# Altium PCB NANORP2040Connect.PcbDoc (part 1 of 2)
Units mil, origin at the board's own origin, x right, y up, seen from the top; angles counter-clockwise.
Board outline 1700 x 700 mil, 4 copper layers (TOP, GND, SIG, BOTTOM), stack 62.441 mil thick; 92 components, 78 nets, 400 pads, 196 vias.
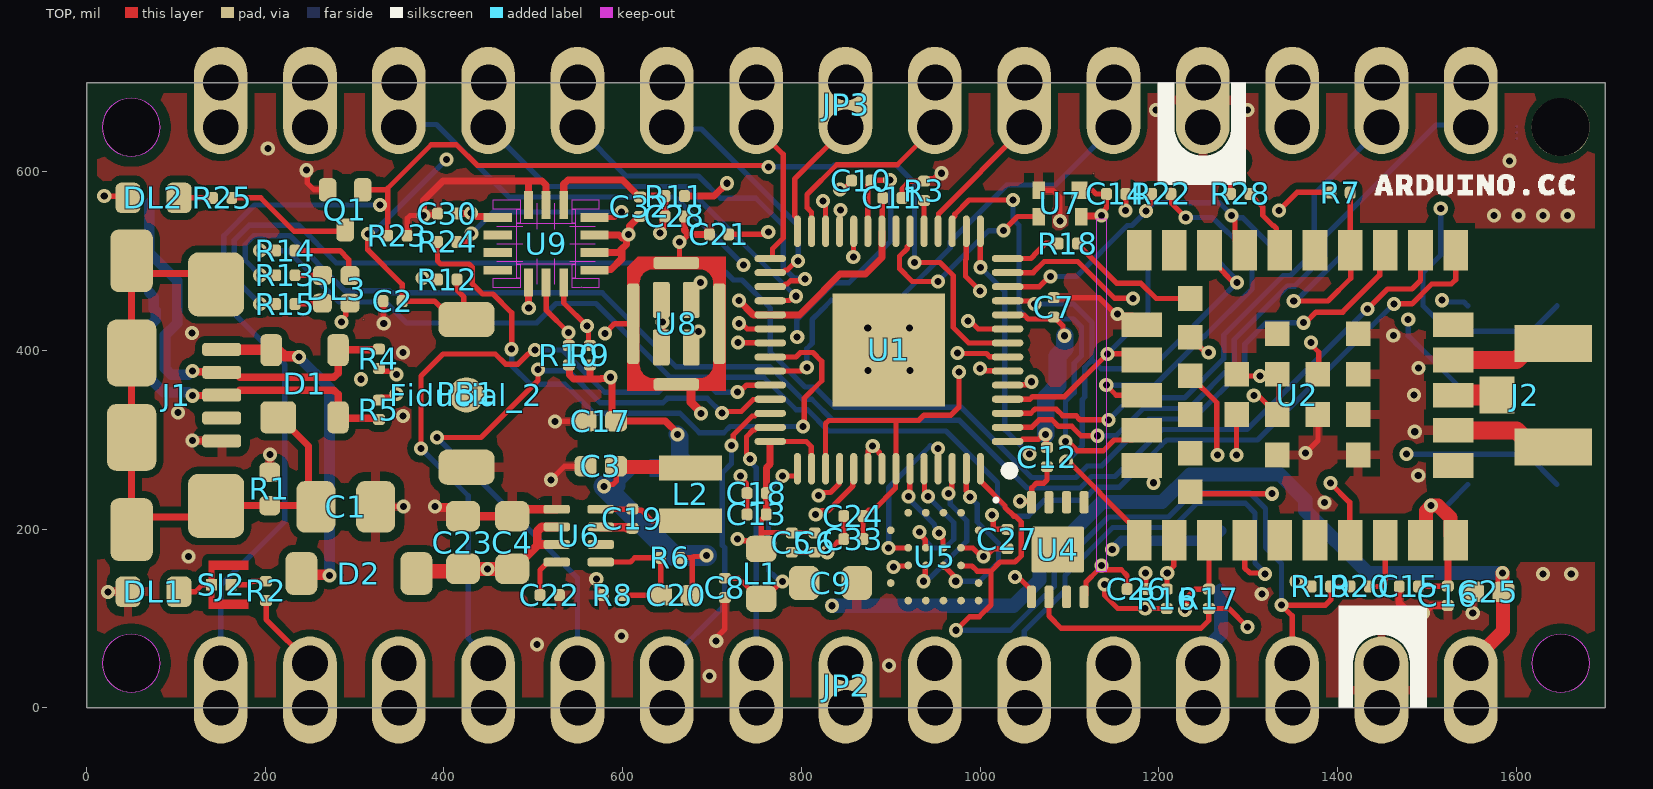
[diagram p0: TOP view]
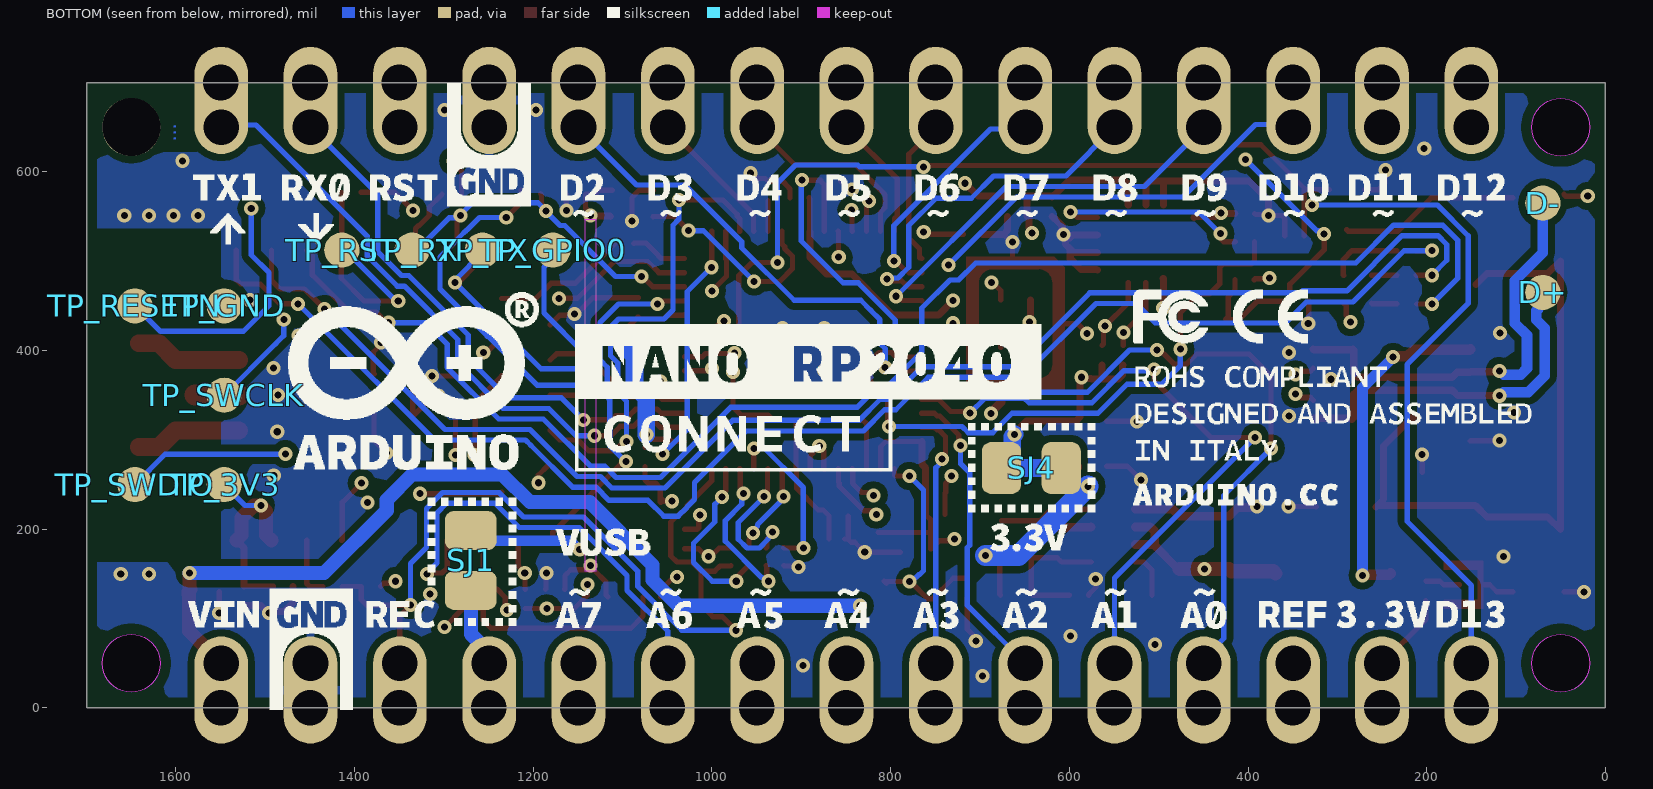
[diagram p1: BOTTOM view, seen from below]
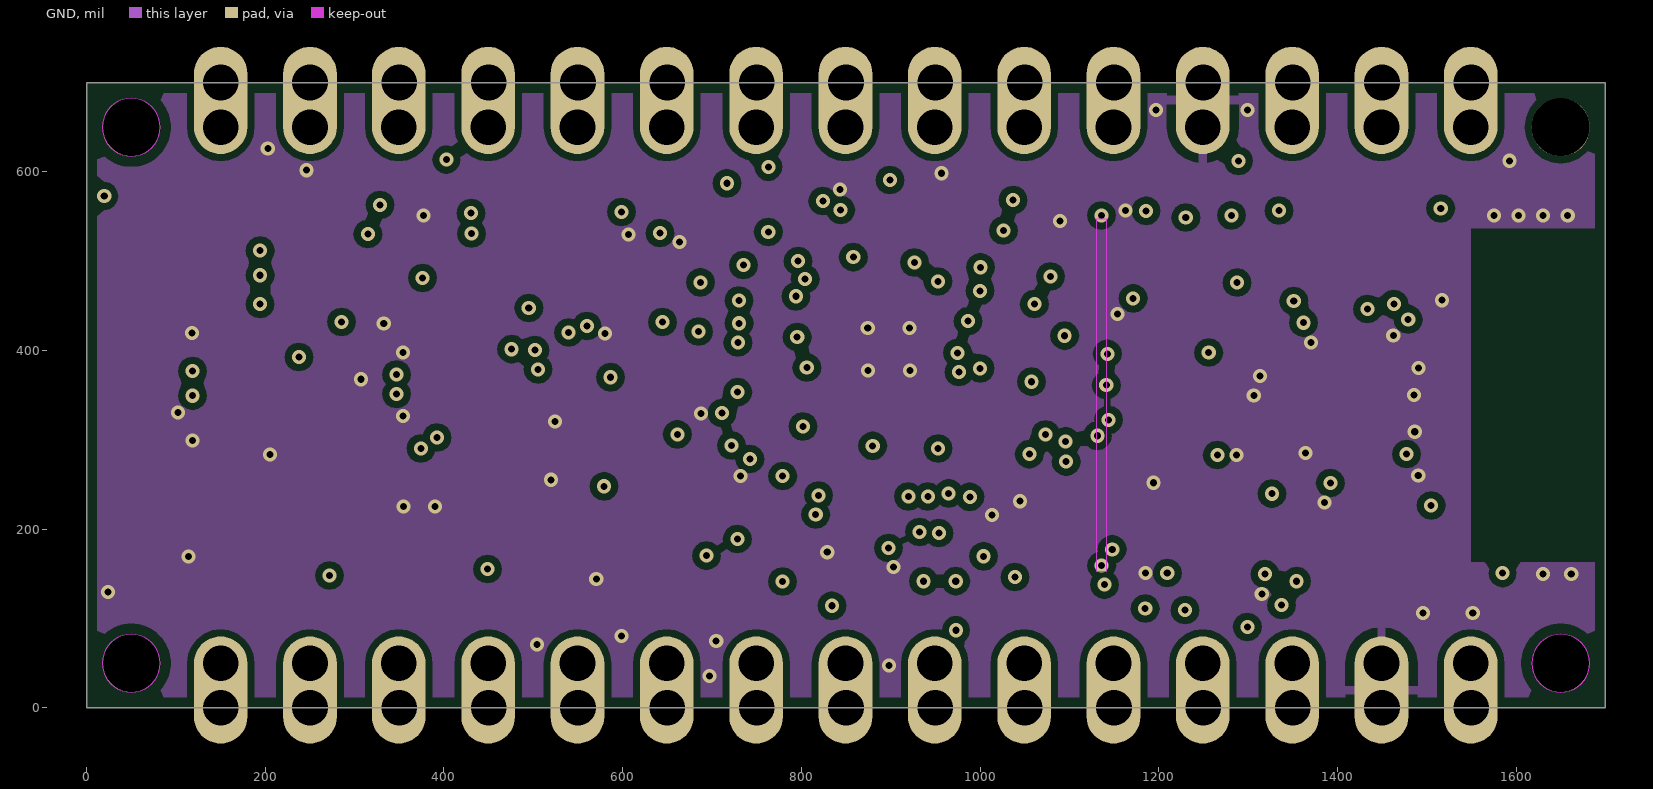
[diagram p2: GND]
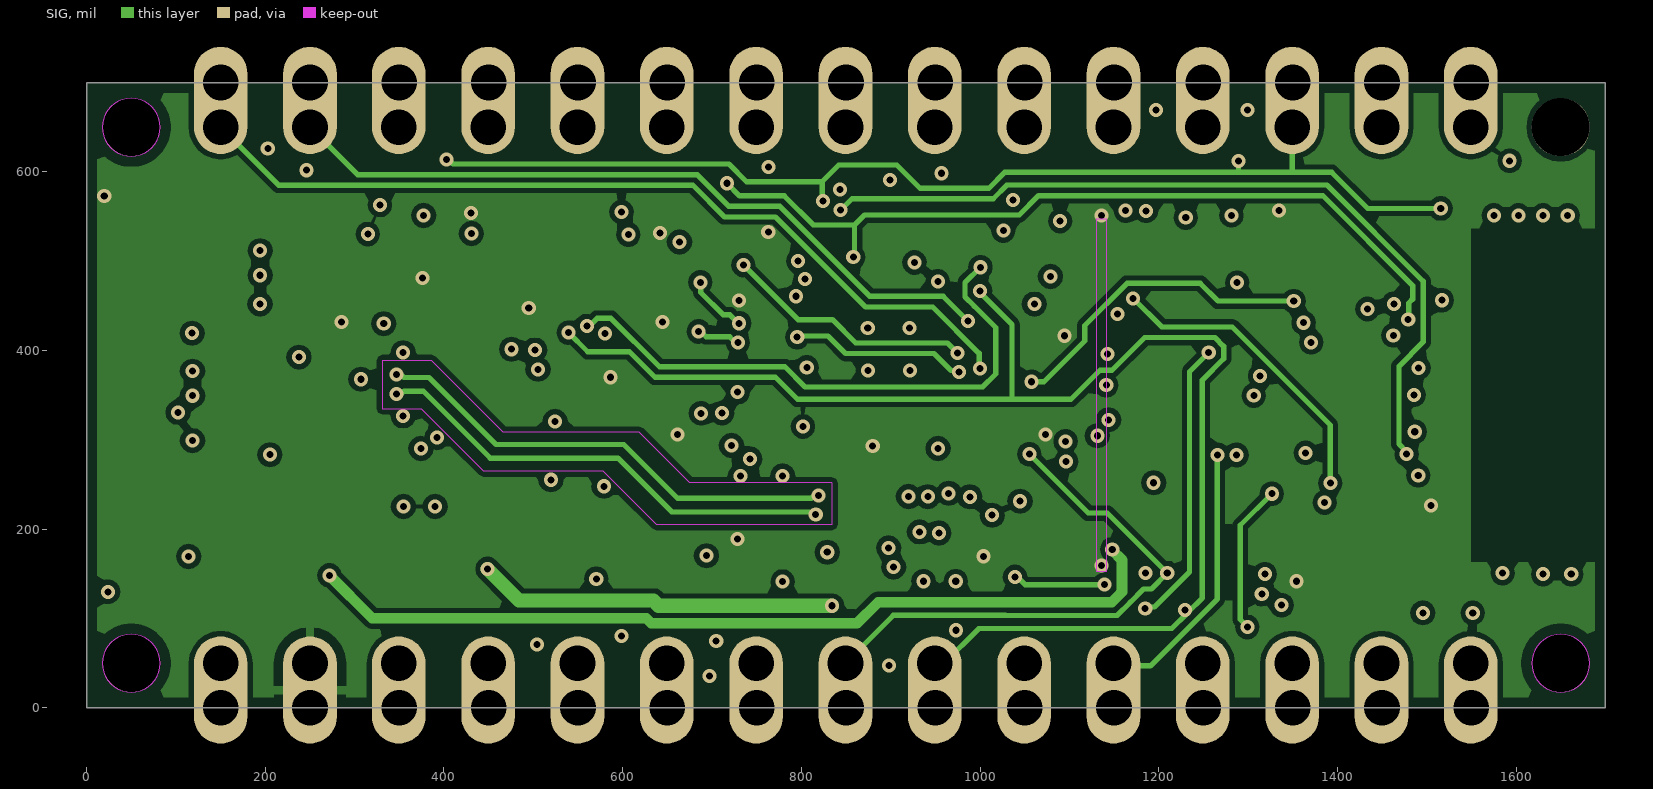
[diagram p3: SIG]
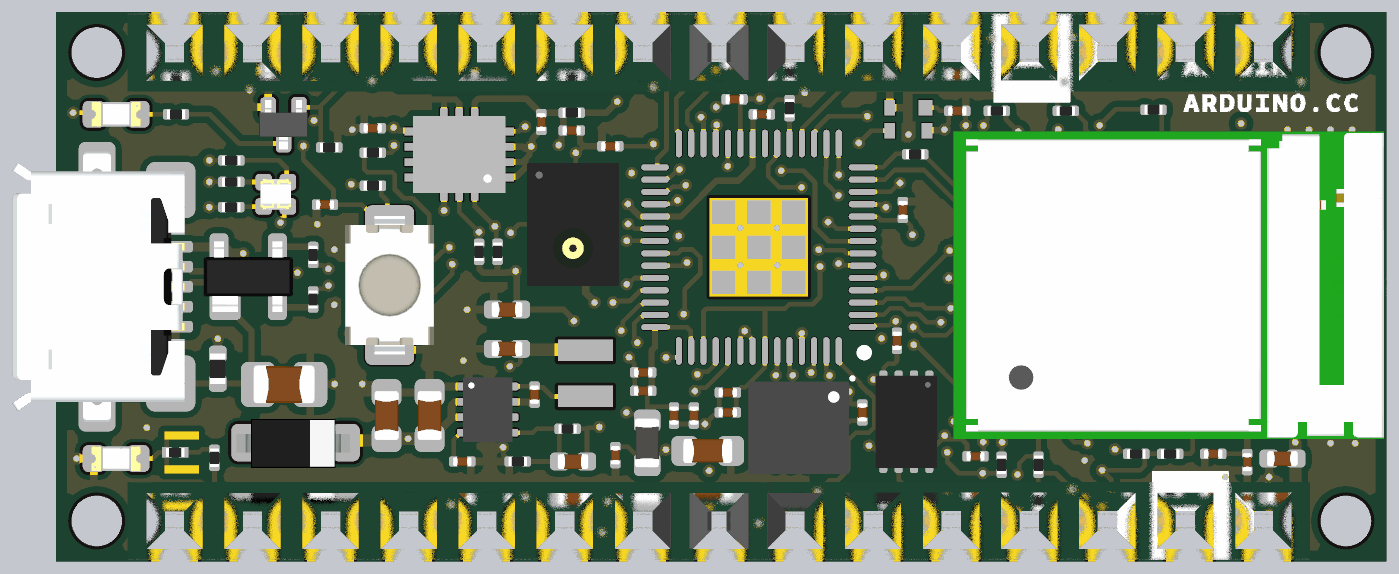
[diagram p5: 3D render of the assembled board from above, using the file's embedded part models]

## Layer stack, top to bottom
Top Solder: solder mask 0.4, Solder Resist, Dk 3.5
TOP: signal copper 0.7087
Dielectric 1: prepreg 5.5118, PP-014, Dk 4.2
GND: signal copper 1.378
Dielectric2: core 47.2441, FR-4, Dk 4.8
SIG: signal copper 1.378
Dielectric3: prepreg 5.5118, PP-014, Dk 4.2
BOTTOM: signal copper 0.7087
Bottom Solder: solder mask 0.4, Solder Resist, Dk 3.5

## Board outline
1700,0 0,0 0,700 1700,700
cut-out: 1650,17.5 ccw(c1650,50) 1682.5,50 ccw(c1650,50) 1650,82.5 ccw(c1650,50) 1617.5,50 ccw(c1650,50)
cut-out: 50,617.5 ccw(c50,650) 82.5,650 ccw(c50,650) 50,682.5 ccw(c50,650) 17.5,650 ccw(c50,650)
cut-out: 50,17.5 ccw(c50,50) 82.5,50 ccw(c50,50) 50,82.5 ccw(c50,50) 17.5,50 ccw(c50,50)

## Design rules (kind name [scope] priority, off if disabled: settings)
BoardOutlineClearance Silks [(OnLayer('Top Overlay') OR OnLayer('Bottom Overlay'))] p1: gap=0.39 ignorepadtopadclearanceinfootprint=FALSE
BoardOutlineClearance MountingHoles [(ObjectKind = 'Pad') And (Name = 'Free-MH')] p2: gap=0 ignorepadtopadclearanceinfootprint=FALSE
BoardOutlineClearance Header_Castellated [((ObjectKind = 'Pad') And (Component = 'JP2')) OR                                                                                    ((ObjectKind = 'Pad') And (Component = 'JP3'))] p3: gap=0 ignorepadtopadclearanceinfootprint=FALSE
BoardOutlineClearance [All] p4: gap=11.81 ignorepadtopadclearanceinfootprint=FALSE
Clearance GND_POLYGONS [(InNamedPolygon('GND_TOP') OR InNamedPolygon('GND_2') OR InNamedPolygon('GND_3') OR InNamedPolygon('GND_BOT'))] p1: gap=7.87 ignorepadtopadclearanceinfootprint=FALSE
Clearance "Generic clearance 0.15mm" [All] p2: gap=5.91 ignorepadtopadclearanceinfootprint=FALSE
ComponentClearance NINA-UFL [InComponent('U2') vs InComponent('J2')] p1: gap=0 collisioncheckmode=3 verticalgap=0 showdistances=FALSE
ComponentClearance [All] p2: gap=0 collisioncheckmode=3 verticalgap=0 showdistances=FALSE
DiffPairsRouting [InDifferentialPairClass('USB')] p1: maxlimit=10 minlimit=5.91 mostfreqgap=10 toplayer_maxgap=5.91 toplayer_prefgap=5.91 toplayer_minwidth=5.91 toplayer_maxwidth=8.27 toplayer_prefwidth=8.27 midlayer14_mingap=9.45 midlayer14_maxgap=9.45 midlayer14_prefgap=9.45 midlayer14_minwidth=5.91 midlayer14_maxwidth=5.91 midlayer14_prefwidth=5.91 bottomlayer_maxgap=5.91 bottomlayer_prefgap=5.91 bottomlayer_minwidth=8.27 bottomlayer_maxwidth=8.27 bottomlayer_prefwidth=8.27 impedanceprofiledriven=TRUE impedanceprofileid={C5D8398E-BCA5-4495-8332-5063613C51E1} impedanceprofilevalue=90.000000 maxuncoupledlength=500
HoleSize [All] p1: absolutevalues=TRUE maxlimit=236.22 minlimit=7.87 maxpercent=80.000 minpercent=20.000
HoleToHoleClearance [All] p1: gap=9.84 allowstackedmicrovias=TRUE
MinimumAnnularRing [All] p1: minimumring=3.94
MinimumSolderMaskSliver [All] p1: minsoldermaskwidth=3.94
NetAntennae Inductor [(ObjectKind = 'Component') And (Comment = 'MAKK2016T3R3M')] p1: netantennaetolerance=393.7
NetAntennae [All] p2: netantennaetolerance=0
PolygonConnect [All] p1: thpad.connectstyle=Relief thpad.reliefconductorwidth=10 thpad.reliefentries=4 thpad.polygonreliefangle="90 Angle" thpad.airgapwidth=10 smdpad.connectstyle=Relief smdpad.reliefconductorwidth=10 smdpad.reliefentries=4 smdpad.polygonreliefangle="90 Angle" smdpad.airgapwidth=10 via.connectstyle=Direct via.reliefconductorwidth=10 via.reliefentries=4 via.polygonreliefangle="90 Angle" via.airgapwidth=10
RoomDefinition TOP [InComponentClass('TOP')] p1: confinementstyle=ConfineIn formatcopy=TRUE lockcomponents=FALSE outline 0,0 1700,0 1700,700 0,700
RoutingVias [All] p1: holewidth=7.87 width=15.75 viastyle="Through Hole" minholewidth=7.87 minwidth=15.75 maxholewidth=7.87 maxwidth=15.75
ShortCircuit SJ4 [Component = 'SJ4' vs (InNet('+3V3') OR InNet('NetC3_2'))] p1: allowed=TRUE
ShortCircuit [All] p2: allowed=FALSE
SilkToSilkClearance [All] p1: silktosilkclearance=7.87
SilkToSolderMaskClearance [IsPad] p1: minsilkscreentomaskgap=3.94 clearancetoexposedcopper=TRUE
SolderMaskExpansion Solder_VIA [IsVia] p1: expansion=4 istentingtop=TRUE
SolderMaskExpansion [All] p2: expansion=4 istentingtop=FALSE
UnRoutedNet [All] p1: checkbadconnections=TRUE
ViasUnderSMD [All] p1: allowed=FALSE
Width [All] p1: maxlimit=196.85 minlimit=5.91 preferedwidth=5.91
20 further rules are at their usual default settings.

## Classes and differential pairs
net class 50ohm: ANT
differential pair class USB: D USB
pad class SMDPaste_OFF: D+-X D--X FD1-P$1 J3-4
differential pair USB: +USB_P -USB_N
differential pair D: +D_P -D_N

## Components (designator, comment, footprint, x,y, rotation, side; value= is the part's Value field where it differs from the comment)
C1 "C0805C472KDRACTU" CAP-0805 290,225 r180 top value=4.7nF
C2 "CL03A104KP3NNNC" CAP-0201 342.39,455.25 r180 top value=100nF
C3 "GRM155R60J106ME05D" CAP-0402 575.59,270.47 r0 top value=10µF
C4 "GRM188R61E106MA73J" CAP-0603 476.38,185.04 r270 top value=10µF
C5 "CL03A104KP3NNNC" CAP-0201 789.37,185.04 r270 top value=100nF
C6 "CL03A104KP3NNNC" CAP-0201 814.96,185.04 r270 top value=100nF
C7 "CL03A104KP3NNNC" CAP-0201 1082.55,448.34 r90 top value=100nF
C8 "CL03A104KP3NNNC" CAP-0201 714.42,134.22 r270 top value=100nF
C9 "CC0603MRX5R5BB106" CAP-0603 832.68,139.76 r180 top value=10µF
C10 "CL03A104KP3NNNC" CAP-0201 867.04,590.09 r180 top value=100nF
C11 "CL03A104KP3NNNC" CAP-0201 901.97,570.87 r0 top value=100nF
C12 "CL03A104KP3NNNC" CAP-0201 1075,280.75 r270 top value=100nF
C13 "GRM033R60J105MEA2D" CAP-0201 749.93,216.63 r180 top value=1µF
C14 "CL03A104KP3NNNC" CAP-0201 1152.35,575.24 r0 top value=100nF
C15 "CL03A104KP3NNNC" CAP-0201 1480.08,135.87 r180 top value=100nF
C16 "CL03A104KP3NNNC" CAP-0201 1523.62,125.45 r270 top value=100nF
C17 "GRM155R60J106ME05D" CAP-0402 575.59,320.87 r0 top value=10µF
C18 "CL03A104KP3NNNC" CAP-0201 750.04,240.29 r180 top value=100nF
C19 "CL03A104KP3NNNC" CAP-0201 610.83,211.81 r270 top value=100nF
C20 "C0402C220J5GAC7411" CAP-0402 660.04,126.18 r0 top value=22pF
C21 "CL03A104KP3NNNC" CAP-0201 707.87,530 r180 top value=100nF
C22 "GRM033R60J105MEA2D" CAP-0201 518.31,126.18 r180 top value=1µF
C23 "GRM188R61E106MA73J" CAP-0603 421.26,185.04 r270 top value=10µF
C24 "CL03A104KP3NNNC" CAP-0201 858.27,214.57 r180 top value=100nF
C25 "C0402C105K8PACTU" CAP-0402 1568.7,129.92 r0 top value=1µF
C26 "CL03A104KP3NNNC" CAP-0201 1175.59,132.87 r0 top value=100nF
C27 "CL03A104KP3NNNC" CAP-0201 1030.71,188.98 r90 top value=100nF
C28 "CL03A104KP3NNNC" CAP-0201 658.31,550.11 r0 top value=100nF
C30 "CL03A104KP3NNNC" CAP-0201 403.54,553.15 r180 top value=100nF
C32 "CL03A104KP3NNNC" CAP-0201 619.4,561.02 r270 top value=100nF
C33 "GRM033R60J105MEA2D" CAP-0201 858.27,188.98 r0 top value=1µF
D1 "PRTR5V0U2X,215" SOT190P230X110-4N 244.02,362.79 r0 top
D2 "D0026-A.2" SOD123-1 304.72,150.39 r180 top
D+ "CMP-018-0005-A.3" TP-1.00MM#1 70,465 r0 top
D- "CMP-018-0005-A.3" TP-1.00MM#1 70,565 r0 top
DL1 "HSMG-C190" LEDC1608X80N-AK 74.8,129.92 r0 top
DL2 "HSMD-C190" LEDC1608X80N-AK 74.8,570.87 r180 top
DL3 "SMLP34RGB2W3" SMLP34RGB2W 279.33,468.5 r90 top
Fiducial_2 "Fiducial mark 1mm with 2mm solder" "Fiducial mark 1mm with circle-Footprint-1" 425.2,350.39 r90 top
J1 "ZX62-AB-5PA(31)" ZX62-AB-5PA 50.39,350 r270 top
J2 "U.FL-R-SMT-1(60)" U.FL-R-SMT-1(60)-1 1641.73,350 r270 top
JP2 "PINHD-1X15-NANO" PINHD-1X14_5VF#1 150,50 r180 top locked
JP3 "PINHD-1X15-NANO-DIGITAL-CASTELLATED" PINHD-1X14_5VF#2 1550,650 r0 top locked
L1 "BLM18PG471SN1D" L-0603 755,150 r90 top
L2 "MAKK2016T3R3M" MAKK2016T3R3M-Footprint-1 675.98,238.98 r90 top
PB1 "PTS820J25KSMTRLFS" C&K_PTS820_NO_HOLES-1 425.2,352.05 r90 top
Q1 "2N7002T-7-F" SOT523 289.37,557.48 r180 top
R1 "CRCW04021M00FKED" RES-0402 205,245 r270 top value=1M
R2 "AC0201FR-07330RL" RES-0201 200.79,130.91 r270 top value=330
R3 "CRCW02010000Z0ED" RES-0201 937.4,578.74 r270 top value=0
R4 "CRCW020127R0FNED" RES-0201 327.16,390.75 r270 top value=27R
R5 "CRCW020127R0FNED" RES-0201 327.16,333.66 r90 top value=27R
R6 "RMCF0201FT976K" RES-0201 653.09,167.98 r0 top value=976k
R7 "AC0201FR-07220KL" RES-0201 1403.54,576.69 r180 top value=220k
R8 "AC0201FR-07220KL" RES-0201 589.17,126.18 r0 top value=220k
R9 "RC0201FR-074K7L" RES-0201 563.38,394.69 r270 top value=4.7k
R10 "RC0201FR-074K7L" RES-0201 539.76,394.69 r270 top value=4.7k
R11 "RC0201FR-074K7L" RES-0201 658.29,572.82 r180 top value=4.7k
R12 "RC0201FR-074K7L" RES-0201 403.74,479.37 r180 top value=4.7k
R13 "AC0201FR-07330RL" RES-0201 222.44,484.25 r180 top value=330
R14 "AC0201FR-07330RL" RES-0201 222.44,511.82 r180 top value=330
R15 "AC0201FR-07330RL" RES-0201 222.31,451.97 r180 top value=330
R16 "CRCW02010000Z0ED" RES-0201 1209.05,122.05 r270 top value=0
R17 "CRCW02010000Z0ED" RES-0201 1256.3,122.05 r270 top value=0
R18 "CRCW02010000Z0ED" RES-0201 1098.43,519.68 r0 top value=0
R19 "RC0201FR-074K7L" RES-0201 1381.65,135.87 r180 top value=4.7k
R20 "CRCW02010000Z0ED" RES-0201 1424.96,135.87 r180 top value=0
R22 "CRCW02010000Z0ED" RES-0201 1202.84,575.24 r180 top value=0
R23 "RMCF0201FT976K" RES-0201 347.9,528.49 r180 top value=976k
R24 "CRCW02010000Z0ED" RES-0201 403.54,521.65 r180 top value=0
R25 "AC0201FR-07330RL" RES-0201 151.57,570.87 r0 top value=330
R28 "CRCW02010000Z0ED" RES-0201 1291.34,575.24 r180 top value=0
SJ1 "SMD solder JUMPER 0805" SJ#1 1270,165 r270 bottom
SJ2 "Solder Jumper 0201 CLOSED with HUG" "Solder Jumper Maze-Footprint-1" 150.59,137.8 r270 top
SJ4 "SMD solder JUMPER CLOSED" SJ#2 642.52,268.5 r180 bottom
TP_3V3 "CMP-018-0005-A.3" TP-1.00MM#2 1546,250 r90 bottom
TP_GND "CMP-018-0005-A.3" TP-1.00MM#2 1546,450 r90 bottom
TP_GPIO0 "CMP-018-0005-A.3" TP-1.00MM#2 1178.15,512.4 r90 bottom
TP_RESETN "CMP-018-0005-A.3" TP-1.00MM#2 1646,450 r90 bottom
TP_RST "CMP-018-0005-A.3" TP-1.00MM#2 1414.37,512.4 r90 bottom
TP_RX "CMP-018-0005-A.3" TP-1.00MM#2 1335.63,512.4 r90 bottom
TP_SWCLK "CMP-018-0005-A.3" TP-1.00MM#2 1546,350 r90 bottom
TP_SWDIO "CMP-018-0005-A.3" TP-1.00MM#2 1646,250 r90 bottom
TP_TX "CMP-018-0005-A.3" TP-1.00MM#2 1256.89,512.4 r90 bottom
U1 "RP2040" QFN40P700X700X90_HS-57N 898.03,400.59 r180 top locked
U2 "NINA-W102-00B" NINA-W102 1373.03,350 r180 top locked
U4 "ATECC608A-MAHDA-T" UDFN8 1087.01,177.17 r180 top
U5 "AT25QL128A-UUE-T" BGA21C50P6X6_301X328X52 949.21,169.29 r270 top
U6 "MP2322GQH" QFN50P150X200X90-8L 550.79,192.72 r0 top
U7 "DSC6111HI2B-012.0000" DFN120P120X89-4M 1089.67,564.63 r180 top
U8 "MP34DT06JTR" HCLGA 660,430 r270 top
U9 "LSM6DSOXTR" VFLGA14 514.34,519.44 r180 top

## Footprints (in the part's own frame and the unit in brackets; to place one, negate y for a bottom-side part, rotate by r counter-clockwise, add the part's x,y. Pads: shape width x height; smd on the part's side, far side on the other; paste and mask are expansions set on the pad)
BGA21C50P6X6_301X328X52 [mm] "BGA, 21-Leads, Body 3.01x3.28mmx0.52mm, Pitch 0.50mm"
  round 0.22 smd mask+0.05: A2(-0.75,1.25) A5(0.75,1.25) A6(1.25,1.25) B1(-1.25,0.75) B3(-0.25,0.75) B4(0.25,0.75) B6(1.25,0.75) C1(-1.25,0.25) C3(-0.25,0.25) C4(0.25,0.25) C6(1.25,0.25) D1(-1.25,-0.25) D3(-0.25,-0.25) D4(0.25,-0.25) D6(1.25,-0.25) E1(-1.25,-0.75) E3(-0.25,-0.75) E4(0.25,-0.75) E6(1.25,-0.75) F2(-0.75,-1.25) F5(0.75,-1.25)
  silkscreen extent -1.66,1.7 -1.56,1.8, body extent -1.51,-1.64 1.51,1.64, height 0.52
C&K_PTS820_NO_HOLES-1 [mm]
  rrect49% 1x1.6 smd mask+0.05: 1(-2.1,0) 2(2.1,0)
  body extent -2.25,-1.45 2.25,1.45, height 2
CAP-0201 [mm] "Chip Capacitor, 2-Leads, Body 0201 (in) 0603 (mm) IPC Medium Density"
  rrect52% 0.31x0.34 smd mask+0: 1(-0.275,0) 2(0.275,0)
  body extent -0.3,-0.15 0.3,0.15, height 0.3
CAP-0402 [mm] "Chip Capacitor, 2-Leads, Body  0402 (in) 1005 (mm), IPC Medium Density"
  rrect52% 0.63x0.58 smd mask+0: 1(-0.435,0) 2(0.435,0)
  body extent -0.5,-0.25 0.5,0.25, height 0.5
CAP-0603 [mm] "Chip Capacitor, Body 0603 imperial,1.6x0.8mm, IPC High Density"
  rrect51% 0.87x0.97 smd mask+0: 1(-0.75,0) 2(0.75,0)
  body extent -0.8,-0.4 0.8,0.4, height 0.8
CAP-0805 [mm] "Chip Capacitor, Body 0805 imperial, 2.0x1.2mm, IPC Medium Density"
  rrect45% 1.11x1.47 smd mask+0: 1(-0.85,0) 2(0.85,0)
  body extent -1,-0.62 1,0.63, height 1.25
DFN120P120X89-4M [mm] "DFN, 4-Leads, Body 1,60x1,20mm, Pitch 1,20mm, IPC Low Density"
  rect 0.45x0.5 smd mask+0.04: 1(-0.555,-0.375)
  rect 0.35x0.5 smd mask+0.04: 2(0.605,-0.375) 3(0.605,0.375) 4(-0.605,0.375)
  body extent -0.8,-0.6 0.8,0.6, height 0.9
"Fiducial mark 1mm with circle-Footprint-1" [mm]
  round 1 smd paste-10 mask+0.5: 1(0,0)
  TOP pour cut-out: 0,1 0.383,0.924 0.707,0.707 0.924,0.383 1,0 1,0 0.924,-0.383 0.707,-0.707 0.383,-0.924 0,-1 0,-1 -0.383,-0.924 -0.707,-0.707 -0.924,-0.383 -1,0 -1,0 -0.924,0.383 -0.707,0.707 -0.383,0.924 0,1
HCLGA [mm]
  rrect22% 1.02x0.48 smd paste+0 mask+0: 1(-0.675,-0.425) 2(0.675,-0.425) 3(0.675,0.425) 4(-0.675,0.425)
  rrect50% 0.35x1.3 smd paste+0 mask+0: 5(-1.725,0) 5(1.725,0)
  rrect50% 2.3x0.35 smd paste+0 mask+0: 5(0,1.225) 5(0,-1.225)
  TOP region: 1.9,0 1.9,1.4 -1.9,1.4 -1.9,-1.1 -1.6,-1.4 1.9,-1.4 1.9,0 1.55,0 1.55,-0.65 1.52,-0.803 1.433,-0.933 1.303,-1.02 1.15,-1.05 1.15,-1.05 -1.15,-1.05 -1.303,-1.02 -1.433,-0.933 -1.52,-0.803 -1.55,-0.65 -1.55,-0.65 -1.55,0.65 -1.52,0.803 -1.433,0.933 -1.303,1.02 -1.15,1.05 -1.15,1.05 1.15,1.05 1.303,1.02 1.433,0.933 1.52,0.803 1.55,0.65 1.55,0.65 1.55,0
  body extent -2,-1.5 2,1.5, height 1
L-0603 [mm] "Chip Inductor - Body 0603 imperial,1.6x0.8mm, IPC High Density"
  rrect51% 0.75x0.87 smd mask+0: 1(-0.71,0) 2(0.71,0)
  body extent -0.8,-0.4 0.8,0.4, height 0.8
LEDC1608X80N-AK [mm]
  rrect50% 0.72x0.87 smd: A(0.725,0) C(-0.725,0)
  body extent -0.8,-0.4 0.8,0.4, height 0.79
MAKK2016T3R3M-Footprint-1 [mm]
  rect 0.7x1.8 smd: 1(-0.75,0) 2(0.75,0)
  body extent -1,-0.8 1,0.8, height 1
NINA-W102 [mm]
  rect 0.7x1.15 smd mask+0.05: 1(4.95,4.125) 2(3.95,4.125) 3(2.95,4.125) 4(1.95,4.125) 5(0.95,4.125) 6(-0.05,4.125) 7(-1.05,4.125) 8(-2.05,4.125) 9(-3.05,4.125) 10(-4.05,4.125) 16(-4.05,-4.125) 17(-3.05,-4.125) 18(-2.05,-4.125) 19(-1.05,-4.125) 20(-0.05,-4.125) 21(0.95,-4.125) 22(1.95,-4.125) 23(2.95,-4.125) 24(3.95,-4.125) 25(4.95,-4.125)
  rect 1.15x0.7 smd mask+0.05: 11(-3.975,2) 12(-3.975,1) 13(-3.975,0) 14(-3.975,-1) 15(-3.975,-2) 26(4.875,-2) 27(4.875,-1) 28(4.875,0) 29(4.875,1) 30(4.875,2)
  rect 0.7x0.7 smd mask+0.05: 31(3.5,2.75) 32(3.5,1.65) 33(3.5,0.55) 34(3.5,-0.55) 35(3.5,-1.65) 36(3.5,-2.75) GND1(-1.28,1.7) GND2(-1.28,0.55) GND3(-1.28,-0.6) GND4(-1.28,-1.75) GND5(-0.13,0.55) GND6(-0.13,-0.6) GND7(1.02,1.7) GND8(1.02,0.55) GND9(1.02,-0.6) GND10(1.02,-1.75) GND11(2.17,0.55) GND12(2.17,-0.6)
  Keep-Out Layer region: 5.865,-5 6.165,-5 6.165,5 5.865,5
  body extent -8.27,-5.05 5.73,4.95, height 3.81
PINHD-1X14_5VF#1 [mil]
  round 27.56 hole 40 mask+7.87: 1(0,50) 2(-100,50) 3(-200,50) 4(-300,50) 5(-400,50) 6(-500,50) 7(-600,50) 8(-700,50) 9(-800,50) 10(-900,50) 11(-1000,50) 12(-1100,50) 13(-1200,50) 14(-1300,50) 15(-1400,50)
  oval 60x120 hole 40 copper offset 0,30 paste-100: 1(0,0) 2(-100,0) 3(-199.41,0) 4(-299.41,0) 5(-399.41,0) 6(-499.41,0) 7(-599.41,0) 8(-699.41,0) 9(-799.41,0) 10(-899.41,0) 11(-999.41,0) 12(-1099.41,0) 13(-1199.41,0) 14(-1299.41,0) 15(-1399.41,0)
  body extent -1454,-50 60,50, height 335
PINHD-1X14_5VF#2 [mil]
  oval 60x120 hole 40 copper offset 0,30 paste-100: 1(-0.59,0) 2(-100.59,0) 3(-200.59,0) 4(-300.59,0) 5(-400.59,0) 6(-500.59,0) 7(-600.59,0) 8(-700.59,0) 9(-800.59,0) 10(-900.59,0) 11(-1000.59,0) 12(-1100.59,0) 13(-1200.59,0) 14(-1300,0) 15(-1400,0)
  round 27.56 hole 40 mask+7.87: 1(0,50) 2(-100,50) 3(-200,50) 4(-300,50) 5(-400,50) 6(-500,50) 7(-600,50) 8(-700,50) 9(-800,50) 10(-900,50) 11(-1000,50) 12(-1100,50) 13(-1200,50) 14(-1300,50) 15(-1400,50)
  body extent -1460,-50 54,50, height 335
QFN40P700X700X90_HS-57N [mm] "QFN, 56-Leads, Body 7,00x7,00mm, Pitch 0,40mm, Thermal Pad 3,10x3,10mm, IPC Medium Density"
  oval 0.9x0.2 smd mask+0.03: 1(-3.375,2.6) 2(-3.375,2.2) 3(-3.375,1.8) 4(-3.375,1.4) 5(-3.375,1) 6(-3.375,0.6) 7(-3.375,0.2) 8(-3.375,-0.2) 9(-3.375,-0.6) 10(-3.375,-1) 11(-3.375,-1.4) 12(-3.375,-1.8) 13(-3.375,-2.2) 14(-3.375,-2.6) 29(3.375,-2.6) 30(3.375,-2.2) 31(3.375,-1.8) 32(3.375,-1.4) 33(3.375,-1) 34(3.375,-0.6) 35(3.375,-0.2) 36(3.375,0.2) 37(3.375,0.6) 38(3.375,1) 39(3.375,1.4) 40(3.375,1.8) 41(3.375,2.2) 42(3.375,2.6)
  oval 0.2x0.9 smd mask+0.03: 15(-2.6,-3.375) 16(-2.2,-3.375) 17(-1.8,-3.375) 18(-1.4,-3.375) 19(-1,-3.375) 20(-0.6,-3.375) 21(-0.2,-3.375) 22(0.2,-3.375) 23(0.6,-3.375) 24(1,-3.375) 25(1.4,-3.375) 26(1.8,-3.375) 27(2.2,-3.375) 28(2.6,-3.375) 43(2.6,3.375) 44(2.2,3.375) 45(1.8,3.375) 46(1.4,3.375) 47(1,3.375) 48(0.6,3.375) 49(0.2,3.375) 50(-0.2,3.375) 51(-0.6,3.375) 52(-1,3.375) 53(-1.4,3.375) 54(-1.8,3.375) 55(-2.2,3.375) 56(-2.6,3.375)
  rect 3.2x3.2 smd paste-5: GND(0,0)
  silkscreen extent -3.55,3.3 -3.3,3.55, body extent -3.5,-3.5 3.5,3.5, height 0.9
QFN50P150X200X90-8L [mm] "QFN, 8-Leads, Body 1,50x2,00mm, Pitch 0,50mm, IPC High Density"
  rrect50% 0.75x0.25 smd mask+0.05: 1(-0.625,0.75) 2(-0.625,0.25) 3(-0.625,-0.25) 4(-0.625,-0.75) 5(0.625,-0.75) 6(0.625,-0.25) 7(0.625,0.25) 8(0.625,0.75)
  body extent -0.8,-1.05 0.8,1.05, height 0.9
RES-0201 [mm] "Chip Resistor, 2-Leads, Body 0201 (in) 0603 (mm) IPC Medium Density"
  rrect52% 0.31x0.34 smd mask+0: 1(-0.275,0) 2(0.275,0)
  body extent -0.3,-0.15 0.3,0.15, height 0.24
RES-0402 [mm] "Chip Resistor, 2-Leads, Body  0402 (in) 1005 (mm), IPC Medium Density"
  rrect51% 0.55x0.58 smd mask+0: 1(-0.475,0) 2(0.475,0)
  body extent -0.5,-0.25 0.5,0.25, height 0.34
SJ#1 [mm]
  rrect45% 1.11x1.47 smd: 1(-0.85,0) 2(0.85,0)
SJ#2 [mm]
  rrect45% 1.11x1.47 smd mask+0: 1(-0.85,0) 2(0.85,0)
  TOP region: -0.31,0.254 -0.31,-0.254 0.31,-0.254 0.31,0.254
SMLP34RGB2W [mm]
  rrect52% 0.54x0.54 smd: 1(-0.395,-0.395) 2(-0.395,0.395) 3(0.395,0.395) 4(0.395,-0.395)
  body extent -0.5,-0.5 0.5,0.5, height 0.2
SOD123-1 [mm]
  rrect50% 0.91x1.22 smd: A(1.635,0) C(-1.635,0)
  body extent -1.78,-0.78 1.92,0.82, height 1.27
"Solder Jumper Maze-Footprint-1" [mm]
  rect 0.34x0.31 smd mask+0: 1(0,-0.275) 2(0,0.275)
  TOP region: -0.424,0.77 -0.424,-0.2 0.424,-0.2 0.424,0.77 0.678,0.77 0.678,-0.35 -0.678,-0.35 -0.678,0.77
  body extent -0.15,-0.3 0.15,0.3, height 0.24
SOT190P230X110-4N [mm]
  rrect33% 1.01x0.91 smd paste+0 mask+0: 1(-0.75,-0.955)
  rrect49% 0.61x0.91 smd paste+0 mask+0: 2(0.95,-0.955) 3(0.95,0.955) 4(-0.95,0.955)
  body extent -1.45,-1.15 1.45,1.15, height 1
SOT523 [mil]
  rrect50% 19.69x25.98 smd: D(0,22.44) G(-19.69,-22.44) S(19.69,-22.44)
  body extent -31,-31 31,31, height 31
TP-1.00MM#1 [mm]
  rrect100% 1x1 smd far side paste-2.54: X(0,0)
TP-1.00MM#2 [mm]
  rrect100% 1x1 smd paste-2.54: X(0,0)
U.FL-R-SMT-1(60)-1 [mm]
  rect 1.05x2.2 smd paste-3: GND(-1.475,0) GND(1.475,0)
  rect 1.05x1 smd paste-3: SIG(0,-1.6)
  body extent -1.5,-1.55 1.5,1.55, height 1.25
UDFN8 [mm] "QFN, 8-Leads, Body 3.00x2.00mm, Pitch 0.50mm, Thermal Pad 1.30x1.50mm, IPC Medium Density"
  rrect54% 0.26x0.64 smd paste+0 mask+0: 1(-0.75,-1.345) 2(-0.25,-1.345) 3(0.25,-1.345) 4(0.75,-1.345) 5(0.75,1.345) 6(0.25,1.345) 7(-0.25,1.345) 8(-0.75,1.345)
  rrect8% 1.5x1.3 smd paste-1.5 mask+0: 9(0,0)
  body extent -1,-1.5 1,1.5, height 0.55
VFLGA14 [mm]
  rect 0.8x0.25 smd mask+0.05: 1(-1.375,0.75) 2(-1.375,0.25) 3(-1.375,-0.25) 4(-1.375,-0.75) 8(1.375,-0.75) 9(1.375,-0.25) 10(1.375,0.25) 11(1.375,0.75)
  rect 0.25x0.8 smd mask+0.05: 5(-0.5,-1.1) 6(0,-1.1) 7(0.5,-1.1) 12(0.5,1.1) 13(0,1.1) 14(-0.5,1.1)
  TOP keep-out region: -0.83,-0.58 -0.83,0.58 0.83,0.58 0.83,-0.58
  TOP keep-out region: -1.5,0.98 -1.5,1.25 -0.74,1.25 -0.74,0.98
  TOP keep-out region: 0.74,0.98 0.74,1.25 1.5,1.25 1.5,0.98
  TOP keep-out region: 0.74,-1.25 0.74,-0.98 1.5,-0.98 1.5,-1.25
  TOP keep-out region: -1.5,-1.25 -1.5,-0.98 -0.74,-0.98 -0.74,-1.25
  TOP keep-out region: -0.83,0.58 -0.83,0.98 -0.74,0.98 -0.74,0.58
  TOP keep-out region: 0.74,0.58 0.74,0.98 0.83,0.98 0.83,0.58
  TOP keep-out region: 0.74,-0.98 0.74,-0.58 0.83,-0.58 0.83,-0.98
  TOP keep-out region: -0.83,-0.98 -0.83,-0.58 -0.74,-0.58 -0.74,-0.98
  TOP keep-out lines w0.01: 1.4,0.5 0.67,0.5 ; 1.4,0 0.67,0 ; 1.4,-0.5 0.67,-0.5 ; 0.25,1.15 0.25,0.42 ; 0.25,-0.42 0.25,-1.15 ; -0.25,1.15 -0.25,0.42 ; -0.25,-0.42 -0.25,-1.15 ; -0.67,0.5 -1.4,0.5 ; -0.67,0 -1.4,0 ; -0.67,-0.5 -1.4,-0.5
  body extent -1.5,-1.25 1.5,1.25, height 0.76
ZX62-AB-5PA [mm]
  rrect49% 0.37x1.11 smd paste+0 mask+0: 1(-1.3,2.56) 2(-0.65,2.56) 3(0,2.56) 4(0.65,2.56) 5(1.3,2.56)
  rrect37% 1.825x1.6 smd paste+0 mask+0: M1(-3.147,2.4) M4(3.147,2.4)
  rrect37% 1.78x1.2 smd paste+0 mask+0: M2(-3.82,0) M3(3.82,0)
  rrect37% 1.9x1.4 smd paste+0 mask+0: M5(-1.2,0) M6(1.2,0)
  body extent -4.4,-2.75 4.4,2.85, height 2.75

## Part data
C1: library part C0059-A.9, "CAP CHIP 0805 4.7nF 1000V X7R 10%", Case Code (Imperial)=0805, Case Code (Metric)=2012, Dielectric=X7R, Manufacturer=KEMET, Tolerance=10%, Voltage=1kV
C2 C5 C6 C7 C8 C10 C11 C12 C14 C15 C16 C18 C19 C21 C24 C26 C27 C28 C30 C32: library part C0113-A.1, "CAP CHIP 0201 100nF 10V X5R 10%", Case Code (Imperial)=0201, Case Code (Metric)=0603, Dielectric=X5R, Manufacturer="Samsung Electro-Mechanics", Tolerance=10%, Voltage=10V
C3 C17: library part C0091-A.8, "CAP CHIP 0402 10UF X5R 6.3V 20%", Case Code (Imperial)=0402, Case Code (Metric)=1005, Dielectric=X5R, Manufacturer=Murata, Tolerance=20%, Voltage=6.3V
C4 C23: library part C0047-A.12, "CAP CHIP 0603 10uF 25V X5R 20%", Case Code (Imperial)=0603, Case Code (Metric)=1608, Dielectric=X5R, Manufacturer=Murata, Manufacturer 2=Samsung, Manufacturer Part Number 2=CL10A226MPCNUBE, Part Number=C1608X5R1A226MT000N, Tolerance=20%, Voltage=25V
C9: library part C0046-A.9, "CAP CHIP 0603 10uF 6V3 X5R 20% Bob", Case Code (Imperial)=0603, Case Code (Metric)=1608, Dielectric=X5R, Manufacturer=Yageo, Tolerance=20%, Voltage=6.3V
C13 C22 C33: library part C0002-A.9, "CAP CHIP 0201 1UF 6.3V X5R 20%", Case Code (Imperial)=0201, Case Code (Metric)=0603, Dielectric=X5R, Manufacturer=Murata, Tolerance=20%, Voltage=6.3V
C20: library part C0029-A.9, "CAP CHIP 0402 22pF 50V C0G 5%", Case Code (Imperial)=0402, Case Code (Metric)=1005, Dielectric=C0G, Manufacturer=KEMET, Manufacturer 2=AVX, Manufacturer Part Number 2=04025A220JAT2A, Tolerance=5%, Voltage=50V
C25: library part C0017-A.9, "CAP CHIP 0402 1uF 10V X5R 10%", Case Code (Imperial)=0402, Case Code (Metric)=1005, Dielectric=X5R, Manufacturer=KEMET, Manufacturer 2=AVX, Manufacturer Part Number 2=GRM155R61A105KE15D, Tolerance=10%, Voltage=10V
D1: library part D0025-A.3, "TVS ARRAY 4LIN.8kV 1pF SOT143B", Manufacturer=Nexperia
D2: "DIODE SCHOTTKY SMD 1A 40V SOD123FL", Manufacturer=Nexperia, Part Number=PMEG6020AELRX
D+ D- TP_3V3 TP_GND TP_GPIO0 TP_RESETN TP_RST TP_RX TP_SWCLK TP_SWDIO TP_TX: library part UT0013-A.2, "Test point 1.00mm"
DL1: library part L0009-A.4, "LED SMD 0603 GREEN/568 15mcd 120^", Manufacturer=Broadcom
DL2: library part L0007-A.4, "LED SMD 0603 ORANGE604 8mcd DIFF.", Manufacturer=Broadcom
DL3: library part L0014-A.5, "LED RGB DIFFUSED PICOLED SMD", Case Code (Imperial)=0404, Case Code (Metric)=1010, Color=Blue,Green,Red, Forward Current=20mA, Forward Voltage=3V, Lens Color=White, Manufacturer="ROHM Semiconductor", Max Operating Temperature=85°C, Min Operating Temperature=-40°C, Package Quantity=1, Test Current=5mA
Fiducial_2: library part UT0024-A.6
J1: library part J0039-A.5, "CONN USB MICRO F/90^ SMD TipoAB 5x1", Manufacturer=Hirose
J2: library part J0042-A.4, "CONN Micro UFL NO PASTE", Manufacturer=Hirose
JP2: library part J0055-A.4, "CONN THD SOCKET F/1/D 15V JANALOG NANO-TYPE"
JP3: library part J0183-A.1, "CONN THD SOCKET F/1/D 15V JDIGITAL NANO-TYPE CASTELLATED"
L1: library part I0006-A.3, "FERRITE SMD 0603 470R 1A 0.2R", Case Code (Imperial)=0603, Case Code (Metric)=1608, Current=1A, DC Resistance (DCR)=200mR, Manufacturer=Murata, Max Operating Temperature=125°C, Min Operating Temperature=-55°C, Package Quantity=1, Test Frequency=100MHz, Tolerance=25%
L2: library part I0045-A.5, "IND CHIP 0806 3.3 uH 20% 1.2A", Case Code (Imperial)=0806, Case Code (Metric)=2016, Current Rating=1.2A, DC Resistance (DCR)=255mR, Inductance=3.3uH, Manufacturer="Taiyo Yuden", Manufacturer 2=Murata, Manufacturer Part Number 2=LQM2MPN3R3NG0L, Max DC Current=1.15A, Max Operating Temperature=105°C, Min Operating Temperature=-40°C, Package Quantity=3000, Resistor Type=Wirewound, Test Frequency=2MHz, Tolerance=20%
PB1: library part B0012-A.3, "PUSHBUTTON SMD PTS820 NO ANCHORS", Color=Black, Manufacturer=C&K, Max Operating Temperature=85°C, Min Operating Temperature=-40°C
Q1: library part T0003-A.2, "MOSFET N-CH 60V 115mA SOT523", Manufacturer="Diodes Inc."
R1: library part R0058-A.5, "RES CHIP 0402 1M 1% 1/16W", Case Code (Imperial)=0402, Case Code (Metric)=1005, Manufacturer=Vishay, Manufacturer 2=Panasonic, Manufacturer Part Number 2=ERJ-2RKF1004X, Power=63mW, Tolerance=1%
R2 R13 R14 R15 R25: library part R0149-A.4, "RES CHIP 0201 330R 1% 1/20W", Case Code (Imperial)=0201, Case Code (Metric)=0603, Manufacturer=Yageo, Manufacturer 2="Samsung Electro-Mechanics", Manufacturer Part Number 2=RC0603F331CS, Power=50mW, Tolerance=1%
R3 R16 R17 R18 R20 R22 R24 R28: library part R0140-A.4, "RES CHIP 0201 0R 1/20W 5%", Case Code (Imperial)=0201, Case Code (Metric)=0603, Manufacturer=Vishay, Power=50mW, Tolerance=5%
R4 R5: library part R0197-A.2, "RES CHIP 0201 27R 1/20W 5%", Case Code (Imperial)=0201, Case Code (Metric)=0603, Manufacturer=Vishay, Manufacturer 2=Panasonic, Manufacturer Part Number 2=ERJ-U01F27R0C, Power=50mW, Tolerance=1%
R6 R23: library part R0198-A.1, "RES CHIP 0201 976k 1/20W 1%", Manufacturer="Stackpole Electronics Inc", Tolerance=1%
R7 R8: library part R0199-A.1, "RES CHIP 0201 220k 1% 1/20W", Manufacturer=Yageo, Tolerance=1%
R9 R10 R11 R12 R19: library part R0151-A.4, "RES CHIP 0201 4K7 1% 1/20W", Case Code (Imperial)=0201, Case Code (Metric)=0603, Manufacturer=Yageo, Power=50mW, Tolerance=1%
SJ1: library part UT0002-A.3, "Solder Jumper 0805"
SJ2: library part UT0033-A.6, Manufacturer=Vishay, Part Number=CRCW02010000Z0ED
SJ4: library part UT0006-A.10, "Solder Jumper shorted pads"
U1: library part U0177-A.6, "IC MICROCONTROLLER RASPBERRY PI", Manufacturer=Raspberry
U2: library part M0002-A.5, "MODULE ESP32 WiFi/BLE", Manufacturer=UBlox
U4: library part U0034-A.4, "IC AUTHENTICATION CHIP UDFN8", Manufacturer=Microchip
U5: library part U0175-A.2, "IC FLASH 128M SPI 21WLCSP", Manufacturer="Adesto Technologies"
U6: library part U0072-A.5, "IC STEP DOWN CONV 1A 22V QFN8", Manufacturer="Monolithic Power Systems"
U7: library part X0013-A.3, "MEMS OSC 12MHz VDD 1.7V to 3.6V VFLGA 1.6mm x 1.2mm", Manufacturer=Microchip
U8: library part U0074-A.4, "SENS MEMS AUDIO OMNIDIRECTIONAL", Manufacturer=STMicroelectronics
U9: library part U0179-A.4, "IMU ACCEL/GYRO I2C/SPI 14VFLGA", Case/Package=LGA-14L, Manufacturer=STMicroelectronics, Max Operating Temperature=+85, Max Supply Voltage=3.6V, Min Operating Temperature=-40, Min Supply Voltage=1.7V

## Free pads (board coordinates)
  round 65 hole 65 unplated: MH(50,50) MH(50,650) MH(1650,50) MH(1650,650)

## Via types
v1: diameter 15.75, hole 7.87, TOP to BOTTOM, tented both sides, 196 vias

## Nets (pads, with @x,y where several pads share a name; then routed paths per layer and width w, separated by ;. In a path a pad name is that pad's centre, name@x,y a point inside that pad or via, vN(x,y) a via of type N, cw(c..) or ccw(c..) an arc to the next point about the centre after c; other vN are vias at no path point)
+1V1: C10.1 C24.1 C33.2 U1.23 U1.45 U1.50 | length 905.4
  TOP w5.91: U1.45@827.16,267.72 827.16,318.17 830.62,321.63 905.9,321.63 ; C33.2@869.09,188.98 869.09,215.04 875.5,221.45 881.07,221.45 905.53,245.9 U1.50@905.53,267.72 ; U1.23@874.41,533.47 874.41,585.93 877.86,589.38 C10.1@877.86,590.09 878.24,590.47 898.82,590.47 v1(899.2,590.85) ; U1.50@905.9,267.72 905.9,321.63 ; v1(976.39,375.82) 976.39,336.63 967.46,327.7 937.37,327.7 931.31,321.63 905.9,321.63
  SIG w5.91: v1(795.4,415) 796.75,416.34 829.72,416.34 849.38,396.68 948.51,396.68 967.49,377.7 974.51,377.7 v1(976.39,375.82)
  BOTTOM w5.91: v1(795.4,415) 794.81,415.59 794.81,434.2 836.36,475.75 853.06,475.75 900.04,522.74 900.04,590.01 v1(899.2,590.85)
+3V3: C5.1 C6.1 C7.1 C11.1 C12.1 C13.1 C14.1 C15.1 C16.1 C17.2 C18.1 C21.1 C26.1 C27.1 C28.1 C30.1 C32.1 DL2.A DL3.1 JP2.2 L1.2 R2.2 R7.2 R9.2 R10.2 R11.2 R12.2 R19.2 SJ4.1 TP_3V3.X U1.1 U1.10 U1.22 U1.33 U1.42 U1.44 U1.48 U1.49 U2.9 U2.10 U4.8 U5.B3 U7.1 U7.4 U8.1 U8.2 U9.5 U9.8 U9.12 | length 2200.2
  TOP w5.91: v1(19.68,572.83) 44.29,572.83 DL2.A@46.26,574.8 ; R2.2@200.79,120.08 200.89,119.97 200.89,99.11 JP2.2@250,50 ; v1(285.43,432.08) 285.43,434.75 290.05,439.37 290.05,450.09 DL3.1@292.91,452.95 ; v1(375.98,481.3) 376.95,480.33 391.95,480.33 R12.2@392.91,479.37 ; C21.1@718.7,530 757.51,530 760.33,532.82 v1(762.99,532.82) ; v1(728.35,188.98) 731.01,188.98 733.05,186.94 746.01,186.94 L1.2@755,177.95 755,194.06 ; C13.1@760.76,216.63 760.76,215.92 755,210.16 755,194.06 ; U1.42@765.16,298.23 805.48,298.23 811.04,292.67 811.04,268.09 U1.44@811.41,267.72 ; C6.1@814.22,196.26 788.79,196.26 757.21,196.27 755,194.06 ; U1.48@874.41,267.72 874.78,268.09 874.78,288.17 v1(879.92,293.31) 887.2,286.03 887.2,284.98 890.16,282.03 U1.49@890.16,267.72 ; U1.22@890.16,533.47 890.53,533.84 890.53,570.26 C11.1@891.14,570.87 ; U5.B3@978.74,179.13 978.84,179.03 991.93,179.03 1001.27,169.68 1006.6,169.68 1015.06,178.15 C27.1@1030.71,178.15 ; U1.1@1030.9,298.23 1045.22,298.23 1047.68,300.69 1065.54,300.69 1070.73,305.88 v1(1073.39,305.88) 1074.19,305.08 1074.19,292.38 C12.1@1075,291.57 ; U1.10@1030.9,439.96 1031.28,439.58 1049.56,439.58 1053.9,435.25 1080.29,435.25 C7.1@1082.55,437.51 1083.03,437.51 1092.91,427.63 1092.91,418.43 v1(1094.79,416.55) ; U7.1@1111.52,579.39 1125.77,579.39 1129.94,575.22 C14.1@1141.52,575.24 1141.5,559.52 1135.83,553.84 v1(1135.83,551.18) ; U4.8@1116.53,124.21 1118.7,126.38 1118.7,141.02 1132.32,154.64 v1@1136.2,154.64 ; v1(1136.2,159.35) v1@1136.2,154.64 ; C26.1@1164.76,132.87 1164.64,132.99 1164.64,148.07 1158.07,154.64 v1@1136.2,154.64 ; v1(1334.65,556.62) 1355.27,577.24 R7.2@1392.72,577.24 ; v1(1354.33,141.73) 1356.99,141.73 1359.26,139.47 1367.69,139.47 1370.83,136.34 R19.2@1370.83,135.87 ; C15.1@1490.91,135.87 1491.11,136.07 1523.42,136.07 C16.1@1523.62,136.28
  TOP w7.87: C30.1@414.37,553.15 414.75,553.52 429.93,553.52 v1(430.3,553.9) 432.44,553.9 436.38,549.95 459.22,549.95 U9.8@460.21,548.97 ; v1(494.88,447.64) 494.77,447.75 494.77,480.39 U9.12@495.16,480.78 ; U9.5@534.05,562.77 534.05,586.23 538.67,590.84 599.82,590.84 616.65,574.02 617.24,574.02 C32.1@619.4,571.85 620.37,572.82 R11.2@647.47,572.82 C28.1@647.48,550.11 ; R10.2@539.76,383.86 540.34,383.28 540.34,372.55 544.95,367.93 563.38,367.93 ; R9.2@563.38,383.86 563.38,367.93 ; v1(586.54,370.08) 585.04,368.57 575.74,368.57 575.1,367.93 563.38,367.93 ; v1@587.42,367.93 588.05,367.3 588.05,325.53 C17.2@592.72,320.87 648.02,320.87 661.18,307.71 v1(661.18,306.18) ; v1(641.73,531.5) 641.73,533.63 645.31,537.21 645.31,547.95 C28.1@647.48,550.11 ; U8.2@643.27,403.43 643.88,404.04 643.88,431.16 v1(644.49,431.77) ; v1@643.27,431.77 U8.1@643.27,456.57 ; v1(730.21,455.99) 746.24,439.96 798.16,439.96 825.19,467 825.19,467.66 843.33,485.8 872.02,485.8 890.16,503.94 U1.22@890.16,533.47 ; C13.1@760.76,216.63 760.81,216.68 760.81,240.24 760.76,240.29 760.76,268.44 765.16,272.84 U1.42@765.16,298.23 ; U7.4@1113.49,549.87 1114.15,550.52 1135.17,550.52 v1(1135.83,551.18) ; C16.1@1523.62,136.28 1523.62,178.74 U2.10@1532.48,187.6
  TOP w15.75: U2.9@1493.11,187.6 1499.01,193.51 1499.01,220.59 v1(1505.05,226.63) 1512.77,226.63 1526.57,212.83 1526.57,193.51 U2.10@1532.48,187.6
  BOTTOM w5.91: v1(1505.05,226.63) 1522.63,226.63 TP_3V3.X@1546,250
  BOTTOM w19.68: v1(661.18,306.18) 663.98,303.38 663.98,280.51 SJ4.1@675.98,268.5 ; v1(1073.39,305.88) 1073.39,347.24 1086.77,360.62 1086.77,393.88 1094.79,401.91 v1(1094.79,416.55)
  other v1: 1003.93,169.68
A0~: JP2.4 U1.38 | length 791.8
  TOP w5.91: v1(374.24,290.36) 374.24,371.34 399.07,396.17 457.35,396.17 468.81,384.71 482.67,384.71 494.11,396.15 494.65,396.15 498.97,400.48 v1(501.64,400.48) ; v1(728.77,353.35) 730.71,353.35 738.58,361.22 U1.38@765.16,361.22
  BOTTOM w5.91: v1(374.24,290.36) 427.17,237.43 427.17,77.82 449.41,55.57 JP2.4@449.41,50 ; v1(501.64,400.48) 532.48,400.48 579.61,353.35 640.24,353.35 645.16,358.27 699.57,358.27 704.49,353.35 v1(728.77,353.35)
A1~: JP2.5 U1.39 | length 760.6
  TOP w5.91: v1(392.13,302.56) 441.4,302.56 505.26,366.42 v1(505.26,378.94) ; v1(711.26,329.87) 713.15,331.75 732.78,331.75 746.12,345.1 764.78,345.1 U1.39@765.16,345.47
  BOTTOM w5.91: v1(392.13,302.56) 549.41,145.28 JP2.5@549.41,50 ; v1(505.26,378.94) 506.76,377.43 538.82,377.43 574.72,341.54 645.13,341.54 650.05,346.46 694.68,346.46 v1(711.26,329.87)
A2~: JP2.6 U1.40 | length 340
  TOP w5.91: v1(721.85,293.69) 723.73,295.58 723.73,305.38 745.12,326.77 747.89,326.77 750.84,329.72 U1.40@765.16,329.72
  BOTTOM w5.91: JP2.6@649.41,50 714.42,115.01 714.42,179.24 711.61,182.05 711.61,263.14 721.85,273.37 v1(721.85,293.69)
A3~: JP2.7 U1.41 | length 288.9
  TOP w5.91: v1(742.36,278.53) 742.36,281.2 738.58,284.98 738.58,303.53 746.08,311.02 747.89,311.02 750.84,313.98 U1.41@765.16,313.98
  BOTTOM w5.91: v1(742.36,278.53) 742.36,275.87 749.41,268.82 JP2.7@749.41,50
A4/SDA~: JP2.8 R9.1 R16.1 U1.15 U2.2 U9.14 | length 1664.6
  TOP w5.91: U9.14@534.03,476.13 534.09,476.08 534.09,453.29 v1(560.01,427.36) ; v1@559.69,427.04 561.7,425.03 561.7,407.2 R9.1@563.38,405.51 ; v1(1000.45,493.19) U1.15@1000.42,533.44 ; R16.1@1209.05,132.87 1209.33,133.15 1209.33,150.61 v1(1209.61,150.89) 1209.61,151.59 1216.93,158.9 1216.93,187.01 U2.2@1217.52,187.6
  SIG w5.91: v1(560.01,427.36) 562.67,427.36 571.32,436 587.03,436 641.14,381.89 781.51,381.89 804.31,359.09 1002.98,359.09 1017.62,373.73 1017.62,425.58 993.66,449.54 983.28,459.92 983.28,476.03 v1(1000.45,493.19) ; JP2.8@849.41,50 903.03,103.62 1028.2,103.62 1028.36,103.46 1153.52,103.46 1168.21,118.15 1183.17,133.12 1191.84,133.12 v1(1209.61,150.89) 1142.47,218.04 1121.11,218.04 v1(1055.19,283.96)
  BOTTOM w5.91: v1(1000.45,493.19) 1027.82,465.82 1027.82,311.33 v1(1055.19,283.96)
